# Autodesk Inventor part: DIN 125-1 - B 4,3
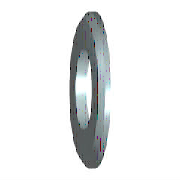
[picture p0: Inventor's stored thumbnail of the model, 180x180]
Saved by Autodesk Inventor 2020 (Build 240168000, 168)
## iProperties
Created: 2010-02
Part Number: DIN 125-1 - B 4,3
Material: Steel, Mild
Document SubType Name: Modeling
Standard: DIN 125-1
Designer: DLutz
Standards Organization: DIN
Language: de-DE
Size Designation: B 4,3
Categories: <MemberInstance><Categories><Category DisplayName="Verbindungselemente" InternalName="e4da775c-781d-43d5-af7c-5136215cf5a6" Mnemonic="FSTN"><Category DisplayNam
Mass: 0.304332 g
Surface Area: 1.28252 cm^2
Volume: 0.0387191 cm^3
Density: 7.86 g/cm^3
Appearance: Metal-Steel
IsCustomPart: 0
Author: DLutz
Revision Number: C
Title: Unterlegscheibe
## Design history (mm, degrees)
chamfer "Chamfer" distance "d4" = 0.2 (= PHH); stored, may be unused: angle "d5" = 45 deg, second distance "d8" = 0.2 (= PHH)
workaxis "Work Axis1"
workplane "Work Plane1"
body "Solid1"
sketch "Sketch"
  geometry: C1 r 4.5 at (0, 0); C2 r 2.15 at (0, 0); 1 further point
  constraints: 2 centre point, 2 coincident
  dimensions: "d0" = 4.3 diameter of C2 (= SD1); "d1" = 9 diameter of C1 (= SD2)
extrude "Body" new body sketch "Sketch" distance "d2" = 0.8 (= SD); taper "d3" = 0 deg
other parameters: "SD1" = 4.3 [user parameter; used in 1 equation term], "SD2" = 9 [user parameter; used in 1 equation term], "SD" = 0.8 [user parameter; used in 1 equation term], "PHH" = 0.2 [user parameter; used in 2 equation terms], "FAWI" = 45 deg [user parameter], "d6" = 0, "d7" = 0, "d9" = 0, "d10" = 0, "NND" = 4 [user parameter]
